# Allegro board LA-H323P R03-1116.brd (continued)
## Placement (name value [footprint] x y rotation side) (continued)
RC460  15_0402_5%  [R_0402]  96.63 36.27 90 bottom
RC462  0_0402_5%  [R_0402]  89.9 34.55 90 bottom
RC467  1K_0201_5%  [R_0201]  117.2 39.85 180 top
RC468  1K_0201_5%  [R_0201]  116.31 41.78 270 top
RC469  1K_0201_5%  [R_0201]  83.68 25.25 90 top
RC470  1K_0201_5%  [R_0201]  85.38 25.25 90 top
RC471  BLM15PX221SN1D 0402  [MURAT_BLM15EG221SN1D_2P]  127.87 54.29 180 top
RC472  4.7K_0201_5%  [R_0201]  113.52 35.3 270 bottom
RC473  20K_0201_5%  [R_0201]  114.24 35.26 0 bottom
RC474  4.7K_0201_5%  [R_0201]  101.62 42.02 0 top
RC475  10K_0201_5%  [R_0201]  102.85 43.24 270 top
RC477  0_0402_5%  [R_0402]  128.2 39.33 180 top
RC480  1K_0402_1%  [R_0402]  131.89 81.82 90 bottom
RC481  1K_0402_1%  [R_0402]  126.45 87.09 90 top
RC482  1K_0402_1%  [R_0402]  131.71 83.6 90 bottom
RC483  100K_0201_5%  [R_0201]  101.22 48.49 180 bottom
RC484  49.9_0402_1%  [R_0402]  123.15 87.09 90 top
RC485  49.9_0402_1%  [R_0402]  123.97 87.09 90 top
RC486  1K_0402_1%  [R_0402]  132.67 82.73 270 bottom
RC487  1K_0402_1%  [R_0402]  130.73 82.73 270 bottom
RC488  1K_0402_1%  [R_0402]  130.17 85.72 270 bottom
RC489  1K_0402_1%  [R_0402]  129.96 82.73 270 bottom
RC491  4.7K_0201_5%  [R_0201]  112.76 35.3 270 bottom
RC492  0_0201_5%  [R_0201]  92.53 43.77 0 top
RC900  10K_0402_5%  [R_0402]  101.71 37.03 90 bottom
RC901  10K_0402_5%  [R_0402]  101.71 35.25 90 bottom
RC916  10K_0201_5%  [R_0201]  100.19 36.94 90 bottom
RC926  10K_0201_5%  [R_0201]  100.95 42.65 90 top
RC934  0_0402_5%  [R_0402]  162.03 21.31 270 top
RC935  49.9_0201_1%  [R_0201]  129.96 76.89 0 bottom
RC936  10K_0201_5%  [R_0201]  114.32 42.44 180 top
RC937  100_0402_5%  [R_0402]  131.52 87.09 90 top
RC938  0_0402_5%  [R_0402]  85.38 38.5 0 top
RC940  10K_0201_5%  [R_0201]  100.19 35.67 90 bottom
RC941  100K_0201_5%  [R_0201]  97.14 40.67 270 bottom
RC942  49.9_0402_1%  [R_0402]  121.57 34.63 0 bottom
RC943  49.9_0402_1%  [R_0402]  122.21 31.52 0 bottom
RC944  49.9_0402_1%  [R_0402]  128.56 34.18 0 bottom
RC945  49.9_0402_1%  [R_0402]  127.82 35.96 180 bottom
RC946  49.9_0402_1%  [R_0402]  127.76 34.18 180 bottom
RC947  49.9_0402_1%  [R_0402]  123.12 30.63 180 bottom
RC948  49.9_0402_1%  [R_0402]  125.9 35.66 270 bottom
RC949  33_0402_5%  [R_0402]  100.28 55.64 0 bottom
RC950  33_0402_5%  [R_0402]  100.08 56.41 0 bottom
RC951  33_0402_5%  [R_0402]  100.28 53.97 0 bottom
RC952  10K_0201_5%  [R_0201]  105.27 42.4 90 top
RC953  10K_0201_5%  [R_0201]  106.54 42.4 90 top
RC954  10K_0201_5%  [R_0201]  105.27 41.13 90 top
RC955  10K_0201_5%  [R_0201]  107.17 42.4 90 top
RC956  10K_0201_5%  [R_0201]  98.83 50.88 180 bottom
RC957  10K_0201_5%  [R_0201]  129.69 40.66 180 bottom
RC958  10K_0201_5%  [R_0201]  100.24 52.39 0 bottom
RC959  10K_0201_5%  [R_0201]  123.43 36.94 90 top
RC961  10K_0201_5%  [R_0201]  123.3 39.56 270 top
RC962  10K_0201_5%  [R_0201]  124.48 38.37 180 bottom
RC963  10K_0201_5%  [R_0201]  123.93 42.98 270 top
RC964  10K_0201_5%  [R_0201]  121.52 42.98 270 top
RC965  10K_0201_5%  [R_0201]  123.17 42.98 270 top
RC966  10K_0201_5%  [R_0201]  122.28 42.98 270 top
RC967  0_0402_5%  [R_0402]  87.92 34.75 0 top
RC977  0_0402_5%  [R_0402]  114.6 36.58 90 bottom
RC978  10K_0201_5%  [R_0201]  121.99 38.37 0 bottom
RC979  100K_0201_5%  [R_0201]  98.83 50.12 180 bottom
RC980  10K_0402_5%  [R_0402]  101.19 55.56 180 top
RC983  100K_0201_5%  [R_0201]  99.04 43.24 270 top
RC984  100K_0201_5%  [R_0201]  99.54 43.73 180 bottom
RC985  20K_0201_5%  [R_0201]  108.82 42.4 90 top
RC986  100K_0201_5%  [R_0201]  99.55 36.25 270 bottom
RC987  100K_0201_5%  [R_0201]  96.67 53.93 180 bottom
RC1154  71.5K_0402_1%  [R_0402]  113.62 35.2 180 top
RC1155  20K_0201_5%  [R_0201]  117.94 38.06 180 bottom
RC1156  499_0402_1%  [R_0402]  99.11 54.54 180 bottom
RC1157  100K_0402_5%  [R_0402]  132.23 86.23 180 bottom
RC1158  1K_0201_5%  [R_0201]  86.01 25.25 90 top
RC1159  1K_0201_5%  [R_0201]  84.31 25.25 90 top
RC1160  49.9_0402_1%  [R_0402]  120.47 33.57 180 bottom
RD1  0_0402_5%  [R_0402]  51.94 26.13 270 top
RD2  0_0402_5%  [R_0402]  52.05 48.2 90 top
RD3  0_0402_5%  [R0402_0OHM]  52.85 25.22 90 top
RD4  0_0402_5%  [R_0402]  54.66 26.13 270 top
RD5  0_0402_5%  [R0402_0OHM]  53.75 25.22 90 top
RD6  0_0402_5%  [R0402_0OHM]  51.16 49.12 270 top
RD7  240_0402_1%  [R_0402]  53.75 60.47 0 top
RD8  1K_0402_1%  [R_0402]  55.08 50.75 180 top
RD9  2_0402_1%  [R_0402]  55.08 51.67 180 top
RD10  1K_0402_1%  [R_0402]  55.08 49.84 180 top
RD11  24.9_0402_1%  [R_0402]  56.75 52.68 180 top
RD19  0_0402_5%  [R_0402]  38.71 22.91 90 top
RD20  0_0402_5%  [R0402_0OHM]  39.6 22.91 90 top
RD21  0_0402_5%  [R_0402]  41.55 45.98 90 top
RD22  0_0402_5%  [R0402_0OHM]  39.54 24.76 180 top
RD23  0_0402_5%  [R_0402]  40.41 24.77 0 top
RD24  0_0402_5%  [R0402_0OHM]  40.65 46.89 270 top
RD25  240_0402_1%  [R_0402]  40.42 59.71 0 top
RD26  1K_0402_1%  [R_0402]  41.51 52.14 90 top
RD27  2_0402_1%  [R_0402]  40.62 52.14 90 top
RD28  1K_0402_1%  [R_0402]  41.58 50.64 180 top
RD29  24.9_0402_1%  [R_0402]  38.69 52.59 90 top
RD32  0_0402_5%  [R0402_0OHM]  65.69 28.42 270 top
RD33  0_0402_5%  [R0402_0OHM]  48.88 28.93 270 top
RE50  10K_0402_5%  [R_0402]  241.54 19.88 90 bottom
RE51  10K_0402_5%  [R_0402]  239.81 21.61 0 bottom
RF1  0_0402_5%  [R0402_0OHM]  253.77 30.3 270 bottom
RG10  15 +-1% 0402  [R_0402]  18.75 115.92 180 bottom
RG12  15 +-1% 0402  [R_0402]  18.75 121.23 180 bottom
RG13  15 +-1% 0402  [R_0402]  18.75 122.02 180 bottom
RG47  1M_0402_5%  [R_0402]  20.13 125.88 180 top
RG56  20K_0402_5%  [R_0402]  19.34 129.94 0 top
RG59  15 +-1% 0402  [R_0402]  18.75 118.18 180 bottom
RG60  15 +-1% 0402  [R_0402]  18.75 118.97 180 bottom
RG61  15 +-1% 0402  [R_0402]  18.75 112.08 180 bottom
RG63  15 +-1% 0402  [R_0402]  18.75 112.87 180 bottom
RG65  15 +-1% 0402  [R_0402]  18.75 115.13 180 bottom
RG67  10K_0402_5%  [R_0402]  175.95 123.59 180 top
RG105  2.2K_0402_5%  [R_0402]  13.5 129.43 0 top
RG108  10K_0402_5%  [R_0402]  18.14 128.75 270 top
RG109  2.2K_0402_5%  [R_0402]  13.5 130.2 0 top
RG110  2.2K_0402_5%  [R_0402]  15.98 131.53 0 top
RG111  2.2K_0402_5%  [R_0402]  16.32 127.85 180 top
RG112  470_0201_5%  [R_0201]  20.21 111.27 180 bottom
RG113  470_0201_5%  [R_0201]  20.21 113.69 180 bottom
RG114  470_0201_5%  [R_0201]  20.21 114.32 180 bottom
RG115  470_0201_5%  [R_0201]  20.21 116.73 180 bottom
RG116  470_0201_5%  [R_0201]  20.21 117.37 180 bottom
RG117  470_0201_5%  [R_0201]  20.21 119.78 180 bottom
RG118  470_0201_5%  [R_0201]  20.21 120.42 180 bottom
RG119  470_0201_5%  [R_0201]  20.21 122.83 180 bottom
RK1  0_0603_5%  [R0603_0OHM]  149.87 48.93 180 bottom
RK2  100K_0402_1%  [R_0402]  168.13 28.16 270 bottom
RK3  0_0402_5%  [R0402_0OHM]  150.3 45.08 180 bottom
RK4  33K_0402_1%  [R_0402]  169.02 27.25 90 bottom
RK6  0_0402_5%  [R_0402]  172.47 42.69 180 bottom
RK7  330K_0402_5%  [R_0402]  171.56 44.47 0 bottom
RK8  0_0201_5%  [R0201_0OHM]  148.27 36.6 180 bottom
RK9  0_0201_5%  [R0201_0OHM]  148.27 35.71 180 bottom
RK10  0_0402_5%  [R_0402]  172.47 41.88 180 bottom
RK12  4.7K_0402_5%  [R_0402]  158.52 30.35 0 top
RK13  4.7K_0402_5%  [R_0402]  158.52 31.11 0 top
RK14  10K_0402_5%  [R_0402]  161.98 50.34 270 bottom
RK17  43_0402_1%  [R_0402]  150.3 41.87 180 bottom
RK21  10K_0402_5%  [R_0402]  167.24 27.25 90 bottom
RK26  100K_0402_5%  [R_0402]  165.58 49.98 180 bottom
RK27  100K_0402_5%  [R_0402]  150.3 40.85 180 bottom
RK28  100K_0402_5%  [R_0402]  171.56 45.36 0 bottom
RK108  10K_0402_5%  [R_0402]  163.67 50.85 270 bottom
RK109  22_0402_5%  [R_0402]  158.59 50.36 270 bottom
RK110  2.2K_0402_5%  [R_0402]  162.92 30.96 270 top
RK111  2.2K_0402_5%  [R_0402]  162.03 30.96 270 top
RK112  2.2K_0402_5%  [R_0402]  161.78 34.77 270 top
RK113  2.2K_0402_5%  [R_0402]  160.89 34.77 270 top
RK115  10K_0402_5%  [R_0402]  160.5 50.36 270 bottom
RK116  100K_0402_5%  [R_0402]  149.36 39 0 bottom
RK117  100K_0402_5%  [R_0402]  145.75 36.08 270 bottom
RL7  1M_0402_5%  [R_0402]  33.43 102.76 0 bottom
RL11  2.49K_0402_1%  [R_0402]  30.63 103 90 bottom
RL15  10K_0402_5%  [R_0402]  41.57 106.7 180 bottom
RL30  374 +-5% 0402  [R_0402]  37.79 100.65 90 bottom
RL31  510_0402_5%  [R_0402]  36.01 100.65 90 bottom
RL55  0_0805_5%  [R0805_0OHM]  30.63 132.48 0 top
RL56  4.7K_0402_5%  [R_0402]  36.9 101.56 270 bottom
RL57  75_0402_1%  [R_0402]  26.14 127.1 270 top
RL58  75_0402_1%  [R_0402]  25.26 127.1 270 top
RL59  75_0402_1%  [R_0402]  25.26 124.53 90 top
RL60  75_0402_1%  [R_0402]  26.14 124.53 90 top
RLED1  680_0402_1%  [R_0402]  5.57 84.32 270 top
RLED2  220_0402_5%  [R_0402]  6.45 93.39 0 bottom
RLED3  0_0402_5%  [R0402_0OHM]  5.82 93.57 270 top
RM6  1K_0402_5%  [R_0402]  41.57 108.22 180 bottom
RM11  15K_0402_5%  [R_0402]  38.67 109.18 270 top
RN3  10K_0402_5%  [R_0402]  225.8 5.18 180 top
RN7  4.7K_0402_5%  [R_0402]  226.28 21.36 0 top
RN15  10K_0402_5%  [R_0402]  230.95 7.76 180 bottom
RS21  100K_0402_5%  [R_0402]  179.22 43.84 90 bottom
RS22  10K_0402_5%  [R_0402]  180.16 44.75 270 bottom
RS46  10K_0402_5%  [R_0402]  190.53 41.5 180 top
RS47  0_0201_5%  [R_0201]  219.43 36.94 90 top
RS48  0_0201_5%  [R_0201]  220.06 36.94 90 top
RS49  0_0201_5%  [R_0201]  217.6 36.94 90 top
RS50  0_0201_5%  [R_0201]  218.23 36.94 90 top
RS53  0_0201_5%  [R_0201]  255.76 20.07 0 bottom
RS54  0_0201_5%  [R_0201]  255.76 19.44 0 bottom
RT3  0_0201_5%  [R0201_0OHM]  203.18 39.56 270 top
RT6  33_0402_5%  [R_0402]  121.57 35.71 0 bottom
RT7  33_0402_5%  [R_0402]  150.91 24.12 0 top
RT8  33_0402_5%  [R_0402]  122.21 32.41 0 bottom
RT9  33_0402_5%  [R_0402]  128.56 35.07 0 bottom
RT10  4.7K_0402_5%  [R_0402]  162.03 22.68 90 top
RT11  100K_0402_5%  [R_0402]  65.53 102.72 90 top
RT12  4.7K_0402_5%  [R_0402]  160.18 24.53 0 top
RT34  0_0201_5%  [R0201_0OHM]  66.25 102.72 270 top
RT35  4.7K_0402_5%  [R_0402]  161.1 23.64 180 top
RU1  100K_0402_1%  [R_0402]  6.97 85.29 90 bottom
RU2  100K_0402_5%  [R_0402]  6.02 82.25 90 bottom
RU3  47K_0402_5%  [R_0402]  6.84 83.21 270 bottom
RV4  200_0402_1%  [R_0402]  137.02 110.1 180 top
RV15  10K_0402_5%  [R_0402]  162.92 90.06 180 bottom
RV16  0_0402_5%  [R_0402]  181.59 128.29 180 top
RV17  10K_0402_5%  [R_0402]  181.59 129.18 180 top
RV20  10K_0402_1%  [R_0402]  159.17 99.18 0 bottom
RV21  10K_0402_1%  [R_0402]  159.17 99.95 0 bottom
RV23  10K_0402_1%  [R_0402]  159.17 98.42 0 bottom
RV26  10K_0402_5%  [R_0402]  160.97 88.39 180 bottom
RV30  10K_0402_5%  [R_0402]  171.89 92.22 180 top
RV31  0_0402_5%  [R0402_0OHM]  170.22 91.13 0 bottom
RV41  40.2_0402_1%  [R_0402]  163.23 115.72 0 top
RV42  40.2_0402_1%  [R_0402]  164.14 116.61 180 top
RV43  60.4_0402_1%  [R_0402]  164.14 117.5 180 top
RV51  4.99K_0402_1%  [R_0402]  153.05 88.44 90 bottom
RV61  10K_0402_1%  [R_0402]  154.72 88.44 90 bottom
RV64  4.99K_0402_1%  [R_0402]  171.92 96.02 180 top
RV65  4.99K_0402_1%  [R_0402]  169.82 95.31 0 bottom
RV67  10K_0402_5%  [R_0402]  172.84 93.15 0 top
RV68  10K_0402_5%  [R_0402]  179.81 127.53 180 top
RV69  100K_0402_5%  [R_0402]  180.58 125.81 90 top
RV70  10K_0402_5%  [R_0402]  157.64 88.67 0 bottom
RV71  10K_0402_5%  [R_0402]  136.13 99.77 0 top
RV72  10K_0402_5%  [R_0402]  156.45 89.35 270 bottom
RV80  4.99K_0402_1%  [R_0402]  173.75 94.04 180 top
RV81  4.99K_0402_1%  [R_0402]  173.75 96.02 180 top
RV82  60.4_0402_1%  [R_0402]  151.36 111.11 270 top
RV83  60.4_0402_1%  [R_0402]  148.26 111.44 270 top
RV84  14.7K_0402_1%  [R_0402]  169.65 99.03 270 bottom
RV85  1K_0402_5%  [R_0402]  132.16 122.45 0 bottom
RV88  10K_0402_5%  [R_0402]  170.7 93.15 0 bottom
RV102  100K_0402_5%  [R_0402]  153.67 96.16 180 top
RV116  1K_0402_1%  [R_0402]  156.83 131.55 90 top
RV117  1K_0402_1%  [R_0402]  146.04 132.67 90 top
RV118  1K_0402_1%  [R_0402]  164.33 132.18 90 top
RV119  1K_0402_1%  [R_0402]  132.68 132.59 270 top
RV120  121_0402_1%  [R_0402]  171.74 132.4 180 bottom
RV121  121_0402_1%  [R_0402]  131.92 132.08 270 bottom
RV123  80.6_0402_1%  [R_0402]  167.37 131.95 270 top
RV125  549_0402_1%  [R_0402]  172.63 126.16 0 bottom
RV126  0_0402_5%  [R_0402]  162.92 89.17 180 bottom
RV127  1.33K_0402_1%  [R_0402]  173.55 127.05 180 bottom
RV175  80.6_0402_1%  [R_0402]  136.46 133.77 180 top
RV200  931_0402_1%  [R_0402]  172.63 125.27 0 bottom
RV201  0_0402_5%  [R_0402]  170.07 96.95 0 bottom
RV202  0_0402_5%  [R0402_0OHM]  170.21 91.98 0 bottom
RV203  2.2K_0402_5%  [R_0402]  165.59 92.79 270 bottom
RV204  2.2K_0402_5%  [R_0402]  161.1 91.06 180 bottom
RV205  2.2K_0402_5%  [R_0402]  159.17 97.66 0 bottom
RV206  2.2K_0402_5%  [R_0402]  159.17 96.9 0 bottom
RV217  100_0402_1%  [R_0402]  115.73 136.34 0 top
RV218  100_0402_1%  [R_0402]  117.38 140.61 0 top
RV375  0_0402_5%  [R_0402]  177.4 127.53 180 top
RV376  2.49K_0402_1%  [R_0402]  132.19 112.6 270 bottom
RV377  0_0402_5%  [R0402_0OHM]  136.65 104.36 90 top
RV378  10K_0402_5%  [R_0402]  181.49 123.51 90 top
RV379  0_0402_5%  [R_0402]  180.58 124.43 270 top
RV380  40.2K_0402_1%  [R_0402]  152.9 101.09 90 top
RV381  4.99K_0402_1%  [R_0402]  171.92 94.05 180 top
RV382  4.99K_0402_1%  [R_0402]  155.64 88.44 90 bottom
RV383  4.99K_0402_1%  [R_0402]  153.81 90.17 90 bottom
RV384  49.9K_0402_1%  [R_0402]  153.81 88.44 90 bottom
RV385  45.3K_0402_1%  [R_0402]  154.72 90.17 90 bottom
RV387  4.99K_0402_1%  [R_0402]  152.13 90.17 90 bottom
RV388  4.99K_0402_1%  [R_0402]  155.64 90.17 90 bottom
RV389  45.3K_0402_1%  [R_0402]  152.13 88.44 90 bottom
RV390  4.99K_0402_1%  [R_0402]  153.05 90.17 90 bottom
RV579  4.7K_0402_5%  [R_0402]  160.97 89.28 180 bottom
RV2437  10K_0402_5%  [R_0402]  147.03 131.29 90 bottom
RV2438  10K_0402_5%  [R_0402]  155.79 130.16 90 bottom
RV2439  10K_0402_5%  [R_0402]  155.56 132.06 180 bottom
RV2440  10K_0402_5%  [R_0402]  147.92 132.97 270 bottom
RV2739  47K_0402_5%  [R_0402]  196.07 126.97 270 top
RV2741  10K_0402_5%  [R_0402]  194.24 127.78 180 top
RV2745  47K_0402_5%  [R_0402]  196.07 124.4 90 top
RV2746  10K_0402_5%  [R_0402]  188.55 127.53 0 top
RV2747  0_0402_5%  [R_0402]  193.33 128.67 0 top
RV2748  0_0402_5%  [R_0402]  195.89 123.59 180 top
RV2751  0_0402_5%  [R_0402]  152.13 102 270 top
RV2752  47K_0402_5%  [R_0402]  132.16 123.34 0 bottom
RV2753  10K_0402_5%  [R_0402]  181.49 125.81 90 top
RV2758  2.2K_0402_5%  [R_0402]  156.9 91.08 270 bottom
RV2759  2.2K_0402_5%  [R_0402]  157.72 91.08 270 bottom
RV2760  2.2K_0402_5%  [R_0402]  158.55 91.08 270 bottom
RV2761  2.2K_0402_5%  [R_0402]  159.37 91.08 270 bottom
RV2762  10K_0402_5%  [R_0402]  153.23 97.22 180 top
RV2763  10K_0402_5%  [R_0402]  153.23 98.05 180 top
RV2764  10K_0402_5%  [R_0402]  153.23 98.88 180 top
RV2765  10K_0402_5%  [R_0402]  163.94 91.54 180 top
RV2766  10K_0402_5%  [R_0402]  149.09 92.03 270 bottom
RV2767  10K_0402_5%  [R_0402]  131.05 94.3 90 bottom
RV2768  10K_0402_5%  [R_0402]  149.91 92.03 270 bottom
RW3  0_0402_5%  [R_0402]  230.03 19.42 0 bottom
RW4  0_0402_5%  [R_0402]  230.03 18.48 0 bottom
RW5  22_0402_5%  [R_0402]  230.03 15.76 0 bottom
RW6  75_0402_5%  [R_0402]  118.09 35.76 90 bottom
RW7  22_0402_5%  [R_0402]  230.03 10.45 0 bottom
RW8  75_0402_5%  [R_0402]  118.91 35.76 90 bottom
RW11  0_0402_5%  [R_0402]  230.03 17.59 0 bottom
RW12  0_0402_5%  [R_0402]  230.03 12.2 0 bottom
RWL1  200K_0402_5%  [R_0402]  248.01 20.52 90 bottom
RWL2  1K_0402_5%  [R_0402]  231 22.23 90 top
SW1  SW TJG-533KQRH SPST DIP H1.55 6P  [SW_TJG-533-V-T-R_6P]  19.8 110.75 180 top
T62  PAD~D  [TPC12]  98.32 46.06 180 bottom
T63  PAD~D  [TPC12]  98.31 47.34 180 bottom
T78  PAD~D  [TPC12]  129.4 78.63 180 bottom
T79  PAD~D  [TPC12]  122.64 76.75 0 top
T81  PAD~D  [TPC12]  99.53 46.46 180 bottom
T90  PAD~D  [TPC12]  97.65 41.3 0 top
T96  PAD~D  [TPC12]  127.63 77.32 180 bottom
T103  PAD~D  [TPC12]  128.98 77.43 180 bottom
T140  PAD~D  [TPC12]  129.05 67.81 180 bottom
T178  PAD~D  [TPC12]  127.66 76.04 90 bottom
T231  PAD  [TPC12]  134.63 97.98 0 top
T232  PAD  [TPC12]  136.18 96.71 0 top
T242  PAD  [TPC12]  135.94 98.56 0 top
T243  PAD  [TPC12]  128.86 95.79 0 top
T254  PAD~D  [TPC12]  95.5 43.71 0 top
T257  PAD~D  [TPC12]  108.2 53.23 0 top
T258  PAD~D  [TPC12]  102.8 52.6 0 top
T276  PAD~D  [TPC12]  121.42 68.31 0 top
T305  PAD~D  [TPC12]  114.66 43.35 0 top
T306  PAD~D  [TPC12]  128.04 64.81 180 bottom
T307  PAD~D  [TPC12]  129.32 64.81 180 bottom
T323  PAD~D  [TPC12]  128.96 81.26 180 bottom
T324  PAD~D  [TPC12]  128.99 82.54 180 bottom
T325  PAD~D  [TPC12]  130.32 80.74 180 bottom
T326  PAD~D  [TPC12]  124.04 80.05 0 top
T327  PAD~D  [TPC12]  120.37 43.52 0 top
T328  PAD~D  [TPC12]  120.14 39.77 0 top
T329  PAD~D  [TPC12]  120.21 41.08 0 top
T354  PAD~D  [TPC12]  100.64 47.62 180 bottom
T365  PAD~D  [TPC12]  128.05 78.53 180 bottom
T366  PAD~D  [TPC12]  127.96 79.83 180 bottom
T367  PAD~D  [TPC12]  131.99 80.87 180 bottom
T368  PAD~D  [TPC12]  129.23 79.99 180 bottom
T369  PAD~D  [TPC12]  129.12 83.85 180 bottom
T370  PAD~D  [TPC12]  127.73 82.35 180 bottom
T371  PAD~D  [TPC12]  130.45 83.86 180 bottom
T372  PAD~D  [TPC12]  127.68 81.07 180 bottom
T377  PAD~D  [TPC12]  102.48 32.89 180 bottom
T402  PAD~D  [TPC12]  15.24 82.95 180 bottom
T403  PAD~D  [TPC12]  13.86 83.66 180 bottom
T404  PAD~D  [TPC12]  13.79 87.41 180 bottom
T405  PAD~D  [TPC12]  14.46 86.25 180 bottom
T406  PAD~D  [TPC12]  13.83 85.08 180 bottom
T408  PAD~D  [TPC12]  121.98 41.55 0 top
T2401  PAD  [TPC12]  154.29 112.52 0 top
T2404  PAD~D  [TPC12]  122.49 39.36 180 bottom
T2405  PAD~D  [TPC12]  121.13 39.57 180 bottom
T2406  PAD~D  [TPC12]  103.49 33.76 180 bottom
TS123  PAD  [TPC12]  188.91 39.78 0 top
TSL1  LAN-8100G 1G  [TAI-T_LAN-8700GS_25P]  31.95 130.08 270 bottom
U4018  APX8131AI-TRG SOT-23  [YB8251ST23_TSOT-23-3]  16.85 138.4 0 top
UA1  -  [ALC3247-CG_MQFN40_5X5]  21.81 40.24 270 top
UC1  WHL-U42_BGA1528  [WHL-U42_BGA_1528P-T]  125.94 86.13 180 bottom
UC2  W25Q128JVSIQ SOP 8P  [ACES_91960-0084L_8P-T]  126.09 32.02 180 bottom
UC3  74AUP1G07DCKR SC70  [74AUP1G07GW_TSSOP5]  112.88 94.37 90 bottom
UC4  TC7SH08FU_SSOP5  [SN74AHC1G08DCKR_SC70-5]  94.09 30.45 270 bottom
UC6  EM5209VF_DFN14_2X3  [TPS22966DPUR_SON14_2X3]  144.83 40.91 0 top
UC7  AOZ1334DI-01 DFN 8P  [TPS22961DNYR_WSON8]  116.02 99.67 180 top
UC11  -  [G753T11U_SOT23-5]  172.61 110.37 180 bottom
UG1  -  [G2895TP1U_TSOT23-6]  63.76 111.59 270 top
UK1  KB9022QD_LQFP128_14X14  [KB9022QC_LQFP128_14X14]  154.57 47.6 270 bottom
UL1  RTL8111HSH-CG  [RTL8166EH-CG_QFN32_4X4]  31.33 106.06 90 bottom
UL2  -  [G524B1T11U_SOT23-5]  43.31 106.29 0 bottom
UT1  SLB9670VQ1.2 FW6.40_VQFN32_5X5  [SLB9670VQ1P2-FW4P4X_VQFN32_5X5]  158.74 21.89 180 top
UU1  -  [TPS25810RVCR_QFN20_4X3]  11.53 83.41 180 bottom
UU2  G518A1TO1U_SOT23-5  [G524B2T11U_SOT23-5]  11.35 91.56 0 bottom
UV1  N16S-GT-S-A2_BGA595  [N16S-GT-S-A2_BGA_595P]  155.9 94.3 90 bottom
UV6  MT51J256M32HF-60:A  [H5GQ1H24AFR-T2L_BGA_170P]  158.13 125.11 0 bottom
UV7  MT51J256M32HF-60:A  [H5GQ1H24AFR-T2L_BGA_170P]  144.68 138.91 180 bottom
UV12  TC7SH08FU_SSOP5  [TC7SH08FUF_SSOP5]  182.7 127.8 270 top
UV15  TC7SH08FU_SSOP5  [TC7SH08FUF_SSOP5]  182.7 125.13 270 top
UV23  MC74VHC1G32DFT2G SC70-5  [NC7ST32P5X_SC70-5]  173.09 94.03 180 bottom
YC1  32.768KHZ_9PF  [Y_1TJF125BJ1A000A_2P]  106.63 35.75 180 bottom
YC2  24MHZ 18PF XRCGB24M000F2P51R0  [Y_XRCGB24M000F2P51R0_4P]  131.79 42.33 90 bottom
YL1  25MHZ 10PF XRCGB25M000F2P34R0  [Y_XRCGB25M000F2P34R0_4P]  34.44 99.87 180 bottom
YV1  27MHZ_10PF_XRCGB27M000F2P18R0  [Y_XRCGB27M000F2P18R0_4P]  162.03 102.78 270 bottom

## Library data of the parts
C11-C14 C19 C117 C118 C140 C153-C156 C193 C554 C557 C570 C575 C593 C594 C4801 C5181-C5186 C5214 C5221 C5222 C5228 C5230-C5233 CA5-CA13 CA19-CA23 CA27-CA30 CA32-CA34 CA36 CA37 CA39 CA41-CA47 CC12 CC13 CC15 CC16 CC27 CC28 CC37-CC42 CC57-CC60 CC88 CC94 CC95 CC122 CC123 CC144 CC154 CC159 CC163 CC256 CC276-CC283 CC292 CC293 CC295 CC297-CC303 CC312 CC314 CC315 CC320 CC325 CC346-CC350 CC354-CC359 CD3 CD4 CD7 CD8 CD10 CD15-CD23 CD62 CD63 CD66 CD67 CD73-CD80 CD82 CD92 CD93 CD95 CE24 CG2 CG8-CG15 CG46 CG47 CK4 CK5 CK8-CK10 CL1 CL3-CL5 CL8-CL14 CL16 CL19 CL20 CL23-CL26 CL28 CL29 CLED1 CLED2 CM17 CM26 CM27 CN3-CN5 CR11 CR13 CS31-CS34 CSS7 CT1 CT3 CT4 CT97 CT98 CT100-CT103 CTS1 CTS3 CTS6 CTS7 CU6-CU11 CV2-CV6 CV8 CV11-CV18 CV20 CV22 CV30 CV38 CV44-CV46 CV51 CV158-CV160 CV165-CV168 CV173-CV175 CV190 CV198 CV199 CV203 CV204 CV209 CV210 CV213 CV216 CV217 CV312 CV315 CV319 CV373-CV388 CV393-CV396 CWL1 CWL2 PC1-PC6 PC8-PC11 PC302-PC304 PC310-PC313 PC316-PC318 PC324-PC327 PC331 PC1003-PC1005 PC1007-PC1010 PC1802 PC1805 PC1806 PC2502-PC2504 PC2507 PCA1-PCA3 PCA6-PCA8 PCB1 PCB4 PCB5 PCB8-PCB14 PCB17-PCB25 PCG1 PCG2 PCG4 PCG8 PCG9 PCG12 PCM1 PCM4-PCM6 PCM14 PCM15 PCM17 PCM18 PCV1 PCV9-PCV14 PCV18-PCV22 PCV24-PCV26 PCV37-PCV51 PCV56 PCV57 PCW2 PCW3 PCW6 PCW7 PCW9 PCW10 PCZ3-PCZ7 PCZ9 PCZ11-PCZ13 PCZ15 PCZ16 PCZ18-PCZ21 PCZ23 PCZ28-PCZ30 PCZ33 PCZ35 PCZ36 PCZ40-PCZ45 PCZ227 PCZ228 PCZ230-PCZ232 R5179 R5180 = C_0402
C18 CA15 CA16 CA31 CA48 CC7-CC11 CC14 CC19 CC20 CC29-CC36 CC43-CC46 CC48-CC51 CC55 CC61-CC63 CC67 CC68 CC71-CC74 CC76 CC80 CC86 CC87 CC89-CC91 CC96-CC98 CC102 CC103 CC117 CC127 CC141 CC142 CC184-CC187 CC261 CC269 CC270 CC274 CC275 CC288-CC291 CC296 CC316 CC319 CC321 CC323 CC324 CC326-CC328 CC331-CC339 CC341-CC343 CC351-CC353 CC360-CC366 CD1 CD2 CD5 CD6 CD9 CD11-CD14 CD24-CD31 CD60 CD61 CD64 CD65 CD68-CD72 CD81 CD83-CD90 CD94 CD96-CD100 CG1 CG3 CG4 CG75-CG78 CK1-CK3 CK11 CL15 CL27 CS1 CS2 CS8-CS10 CS23 CS24 CSS5 CSS6 CT2 CT5 CU4 CU12 CV31 CV34 CV52 CV53 CV55 CV60 CV121 CV133 CV161-CV164 CV169-CV172 CV200-CV202 CV205-CV208 CV211 CV212 CV214 CV215 CV218-CV223 CV311 CV313 CV314 CV316-CV318 CV320 CV321 CV389-CV392 PC1006 PC1016 PCM3 PCM7 PCM16 PCM19-PCM21 PCV28-PCV32 PCW1 PCW4 PCW8 PCW16 PCZ140-PCZ146 PCZ167-PCZ214 = C_0201
C174 = C_MP2VLPS330MC4R2
CA24-CA26 CC82 CC111 CC112 CC115 CC116 CC134 CC140 CC317 CC318 CC329 CS27 CU3 CV7 CV10 CV35 CV61 PC301 PC305-PC309 PC314 PC315 PC319 PC322 PC323 PC328-PC330 PC1001 PC1011-PC1014 PC1801 PC1803 PC1804 PC2501 PC2505 PC2506 PCA4 PCA5 PCG5 PCG10 PCM2 PCM8-PCM13 PCV52 PCV58-PCV61 PCV66-PCV76 PCW5 PCW11-PCW14 PCW17-PCW19 PCZ1 PCZ31 PCZ32 PCZ34 PCZ37 PCZ47 PCZ70-PCZ82 PCZ85-PCZ91 PCZ93-PCZ104 PCZ109-PCZ117 PCZ119 PCZ127 PCZ131 PCZ132 PCZ134-PCZ137 PCZ150 PCZ154 PCZ155 PCZ157-PCZ166 PCZ233-PCZ240 PCZ243-PCZ247 = C_0603
CC81 CC170 CC171 CU13 PCV53 = C_0805
CG71-CG74 PH1 PHA1 PHG1 PHZ1-PHZ3 PR1-PR6 PR9 PR10 PR13-PR17 PR20 PR21 PR301 PR304 PR305 PR307 PR309 PR310 PR312 PR313 PR1002 PR1004 PR1005 PR1008-PR1010 PR1801 PR1803 PR1805 PR1806 PR2502-PR2507 PRA1 PRA7 PRA8 PRB2 PRB3 PRB15-PRB17 PRB20 PRB21 PRG1 PRG7 PRG8 PRM2 PRM6 PRM7 PRM9-PRM11 PRV3 PRV5 PRV6 PRV8-PRV11 PRV13-PRV15 PRV18 PRV22 PRV24 PRV26-PRV33 PRW1-PRW5 PRW8-PRW10 PRZ1-PRZ6 PRZ8 PRZ10 PRZ11 PRZ13 PRZ14 PRZ17-PRZ24 PRZ26 PRZ28-PRZ31 PRZ33 PRZ35 PRZ36 PRZ38 PRZ39 PRZ41 PRZ43 PRZ45 PRZ48 PRZ49 PRZ51 PRZ52 PRZ54 PRZ56 PRZ59 PRZ63-PRZ75 PRZ80 PRZ81 PRZ88 PRZ90 PRZ98-PRZ100 PRZ104-PRZ109 R23 R28 R126 R166 R203 R207 R215 R295 R1088 R1089 R5092 R5093 R5176 R5187 R5201 R5202 R5273 RA1 RA2 RA4-RA10 RA13-RA17 RA23 RA24 RA26 RA37-RA42 RA53 RC1-RC3 RC5 RC6 RC14 RC32 RC38-RC40 RC72 RC76 RC81 RC82 RC92 RC96 RC98 RC102 RC113 RC116 RC119 RC120 RC142 RC150 RC154 RC173 RC179-RC181 RC185 RC188 RC193 RC215 RC216 RC369 RC388-RC391 RC393 RC398 RC399 RC402 RC421 RC429 RC447 RC448 RC456 RC457 RC460 RC462 RC477 RC480-RC482 RC484-RC489 RC900 RC901 RC934 RC937 RC938 RC942-RC951 RC967 RC977 RC980 RC1154 RC1156 RC1157 RC1160 RD1 RD2 RD4 RD7-RD11 RD19 RD21 RD23 RD25-RD29 RE50 RE51 RG10 RG12 RG13 RG47 RG56 RG59-RG61 RG63 RG65 RG67 RG105 RG108-RG111 RK2 RK4 RK6 RK7 RK10 RK12-RK14 RK17 RK21 RK26-RK28 RK108-RK113 RK115-RK117 RL7 RL11 RL15 RL30 RL31 RL56-RL60 RLED1 RLED2 RM6 RM11 RN3 RN7 RN15 RS21 RS22 RS46 RT6-RT12 RT35 RU1-RU3 RV4 RV15-RV17 RV20 RV21 RV23 RV26 RV30 RV41-RV43 RV51 RV61 RV64 RV65 RV67-RV72 RV80-RV85 RV88 RV102 RV116-RV121 RV123 RV125-RV127 RV175 RV200 RV201 RV203-RV206 RV217 RV218 RV375 RV376 RV378-RV385 RV387-RV390 RV579 RV2437-RV2440 RV2739 RV2741 RV2745-RV2748 RV2751-RV2753 RV2758-RV2768 RW3-RW8 RW11 RW12 RWL1 RWL2 = R_0402
CL2 = C_1808
CLRP1-CLRP3 JP6 = SHORTPADS: User Part Number: PART#
CS16 = CK0402101V05_0402-2
D1 DM15 = YSLC05CH_SOT23-3
D6 D7 = PESD5V0U2BT_SOT23-3
D21 D22 DG1 DM16 = AZ1045-04F_DFN2510P10E-10-9
D31-D33 = L05ESDL5V0NA-4_SLP2510P8-10-9
DA6 DA7 = L03ESDL5V0CC3-2_SOT23-3
DC1 = DAN202U_SC70-3
DC3 DC4 DH2 DH4 DH5 DK2 = CH751H-40PT_SOD323-2
DC6 PD1 PD2 = L30ESD24VC3-2_SOT23-3
DL1 DM1 DM5 = AZC199-02SPR7G_SOT23-3
DM12 DM13 = YSUSB2P0-5_SOT-23-6-6
DT2 = AZC099-04SPR7G_SOT23-6
DV1 DV3 DV4 = RB751S40T1G_SOD523-2
FD1-FD4 = FIDUCIAL_C40M80
FG1 FG2 FG4 = AP2330W-7_SC59-3
FU1 = F_MF-MSMF050-2
H1 = H_2P5N
H2 = H_2P5X2P8N
H4 H5 = H_3P2
H6-H11 = H_5P0-G
H13-H15 = H_2P3-G
H17 = H_2P5-G
JCMOS1 PR1802 PRA2 PRA6 PRA9 PRB5 PRB7 PRB9 PRB10 PRB13 PRB14 PRG2 PRG3 PRG6 PRG9 PRM1 PRM4 PRM5 PRV12 PRV20 PRZ76 PRZ77 PRZ79 PRZ85 PRZ87 PRZ102 PRZ103 R24 = R_0603
JCR JHP = ACES_51524-0060N-001_6P
JDIMM1 = FOX_AS0A827-H2RB-7H_260P-T
JDIMM2 = FOX_AS0A827-H2SB-7H_260P-T
JEDP = ACES_51540-03001-001_30P
JFAN = ACES_50271-0040N-001_4P
JFPR JHDD = ACES_51522-00801-001_8P
JHDMI = LOTES_AHDM0064-P001A_19P
JIO = ACES_51522-02601-001_26P
JKB = ACES_50690-0320N-P01_32P
JKBL = ACES_51575-00401-001_4P
JL33 JPHW9 PJ1802 PJV1 PJW1 = JUMP_43X79
JLAN = SINGA_2RJ3081-1A8211F_12P-T
JPHW1 PJ302 PJ305 PJ1002 PJM2 PJW2 = JUMP_43X118
JSPK = ACES_50278-00401-001_4P
JSSD = ARGOS_NFSM0-S6715-TPH4_67P
JTC1 = SINGA_2UB3C02-002111F_24P-T
JTP1 = ACES_51522-01001-001_10P
JTP2 = JXT_FP202DH-004M10M_4P
JWLAN = LOTES_APCI0019-P003H_67P
L12-L14 LM3 LM5-LM7 = MURAT_DLM0NSN900HY2D_4P
LA6 = MURAT_BLM15PX471SN1D_2P
LED1 LED2 = LED_LTW-110DC5-C_3P
LK1 LK2 = MURAT_BLM15BD601SN1D_2P
LL2 = TAI-T_HPC252012F-1R0Y_2P
LV5 LV7 = MURAT_BLM18PG300SN1D_2P
LV6 = KC_FBMA-L11160808601LMA10T_2P
PCB6 PCB7 PCB15 PCB16 PCV5 PCV6 PCV15 PCV16 = C_0603-S3
PCV2 PCV3 PCZ26 PCZ229 = C_6P3X4P5
PCV34 PCV35 = C_X
PCZ68 PCZ69 PCZ215 = C_D1
PCZ248 = C_D7
PD3 = LUDZS3P6BT1G_SOD323-2
PDB1 = BAS40CW_SOT323-3
PDB2 = RB751V-40_SOD323-2
PJ303 = JUMP_43X39
PJ1801 PJ2501 PJ2502 PJM3 = JUMP_43X39_0805
PJP1 = ACES_51483-00801-001_8P-T
PJPB1 = OCTEK_BTJ-08TFBRZB_8P
PL11-PL14 PL305 PL306 PLM2 PLZ3 = 5A_Z80_0805_2P
PL301 PLG1 PLZ1 PLZ2 = L_7X7X3_M
PL302 = L_5X5X3_M_2P
PL303 PL304 PL1002 PL1003 = 3A_Z120_0603_2P
PL1001 PLM1 PLW1 = L_7X7X3_M_2P
PL1801 PL2501 = CHILI_MHCD252012A-1R0M-A8S_2P
PLA1 = L_5X5X3_M
PLB1 = VISHAY_IHLP-2525CZ-01_2P
PLB11 = L_4X4X2_F_2P
PLV3 PLV4 = L_7X7X4_M
PQ2 = L2N7002DW1T1G_SC88-6
PQA1 PQB1 PQM1 = AONH36334_DFN3X3A8-10
PQB2 = 2N7002KW_SOT323-3
PQB11 PQG2 PQZ2 PQZ4 = Q_N_DFN56-8-5
PQB12 PQB13 = AON7506_DFN33-8-5
PQG1 PQZ1 PQZ3 = AON6380_DFN5X6-8-5
PQV1 PQV2 = FDPC5030SG_POWERCLIP56-8-10
PR18 PR302 PR306 PR311 PR1001 PR1003 PR1006 PR1804 PR2501 PRB18 PRB19 PRB22 PRM8 PRM12 PRV1 PRW7 PRZ15 PRZ25 PRZ47 PRZ50 PRZ93-PRZ95 R5261 R5262 RD3 RD5 RD6 RD20 RD22 RD24 RD32 RD33 RF1 RK3 RLED3 RV31 RV202 RV377 = R0402_0OHM
PR19 PRZ53 RC427 = R_0805
PR303 PR308 PR1007 PRA4 PRB6 PRB12 PRG4 PRM3 PRV7 PRV17 PRW6 PRZ82 PRZ84 = R_1206
PRB1 PRB11 = R_1206_4P-D
PTPM1 T62 T63 T78 T79 T81 T90 T96 T103 T140 T178 T231 T232 T242 T243 T254 T257 T258 T276 T305-T307 T323-T329 T354 T365-T372 T377 T402-T406 T408 T2401 T2404-T2406 TS123 = TPC12
PU301 = SY8284BRAC_QFN20_3X3
PU302 = SY8270CTMC_QFN13_4X3
PU1001 PUW1 = SY8286RAC_QFN20_3X3
PU1801 PU2501 = SY8032ABC_SOT23-6
PUA1 PUG1 PUZ2 PUZ3 = RT9610CGQW_WDFN8_2X2
PUB1 = BQ24725ARGRR_QFN20_3P5X3P5
PUM1 = G5616BRZ1U_TQFN20_3X3
PUV1 = RT8812AGQW_WQFN20_3X3
PUZ1 = RT3602AJGQW_WQFN48_6X6
Q9 = MMBF170-7-F_SOT23-3
Q21 = EM5209VF_DFN14_3X2
Q4108 QV3 = 2N7002K_SOT23-3
Q5001 = DMN65D8LDW-7_SOT363-6
QA2 = MMBT3904WH_SOT323-3
QC1 QC7 QG2 = 2N7002DWH_SOT363-6
QG1 = 2N7002KDW_SOT363-6
QG4 QU3 QV146 = 2N7002_SOT23-3
QS1 QWL2 = SSM3K7002FU_SC70-3
QV2 = 2N7002KDWH_SOT363-6
QV5 = LBSS138LT1G_SOT23-3
QV20 QV26 QWL1 = PJ2301_SOT23-3
QV30 = 2N7002DW-7-F_SOT363-6
QV50 = 2N7002W-T-R7_SOT323-3
R163 R170 R171 R173 R5175 R5260 R5263-R5272 RC4 RC49-RC51 RC77 RC91 RC93 RC94 RC100 RC101 RC103-RC107 RC115 RC117 RC118 RC122-RC124 RC127 RC128 RC132 RC165 RC183 RC187 RC201 RC218 RC226 RC227 RC357 RC360 RC374 RC379-RC384 RC401 RC403 RC404 RC409 RC410 RC434 RC459 RC467-RC470 RC472-RC475 RC483 RC491 RC492 RC916 RC926 RC935 RC936 RC940 RC941 RC952-RC959 RC961-RC966 RC978 RC979 RC983-RC987 RC1155 RC1158 RC1159 RG112-RG119 RS47-RS50 RS53 RS54 = R_0201
R201 R202 RA33-RA36 RK1 = R0603_0OHM
R259 R5094 R5178 RC108-RC110 RC230 RK8 RK9 RT3 RT34 = R0201_0OHM
RA51 RA52 RA54 = R0603_0OHM-NPM
RC189-RC191 RL55 = R0805_0OHM
RC471 = MURAT_BLM15EG221SN1D_2P
SW1 = SW_TJG-533-V-T-R_6P
TSL1 = TAI-T_LAN-8700GS_25P
U4018 = YB8251ST23_TSOT-23-3
UA1 = ALC3247-CG_MQFN40_5X5
UC1 = WHL-U42_BGA_1528P-T
UC2 = ACES_91960-0084L_8P-T
UC3 = 74AUP1G07GW_TSSOP5
UC4 = SN74AHC1G08DCKR_SC70-5
UC6 = TPS22966DPUR_SON14_2X3
UC7 = TPS22961DNYR_WSON8
UC11 = G753T11U_SOT23-5
UG1 = G2895TP1U_TSOT23-6
UK1 = KB9022QC_LQFP128_14X14
UL1 = RTL8166EH-CG_QFN32_4X4
UL2 = G524B1T11U_SOT23-5
UT1 = SLB9670VQ1P2-FW4P4X_VQFN32_5X5
UU1 = TPS25810RVCR_QFN20_4X3
UU2 = G524B2T11U_SOT23-5
UV1 = N16S-GT-S-A2_BGA_595P
UV6 UV7 = H5GQ1H24AFR-T2L_BGA_170P
UV12 UV15 = TC7SH08FUF_SSOP5
UV23 = NC7ST32P5X_SC70-5
YC1 = Y_1TJF125BJ1A000A_2P
YC2 = Y_XRCGB24M000F2P51R0_4P
YL1 = Y_XRCGB25M000F2P34R0_4P
YV1 = Y_XRCGB27M000F2P18R0_4P

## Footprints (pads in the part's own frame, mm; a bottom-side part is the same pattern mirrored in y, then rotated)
2N7002_SOT23-3
  oval 1.016x1.524 smd: 1(0,0) 2(0.965,2.083) 3(-0.965,2.083)
2N7002DW-7-F_SOT363-6
  oval 0.432x0.61 smd: 1(0,0) 2(0.65,0) 3(1.3,0) 4(1.3,1.9) 5(0.65,1.9) 6(0,1.9)
2N7002DWH_SOT363-6
  oval 0.356x0.889 smd: 1(0,0) 2(0.65,0) 3(1.3,0) 4(1.3,1.6) 5(0.65,1.6) 6(0,1.6)
2N7002K_SOT23-3
  oval 1.016x1.524 smd: 1(0,0) 2(0.965,2.083) 3(-0.965,2.083)
2N7002KDW_SOT363-6
  oval 0.356x0.889 smd: 1(0,0) 2(0.65,0) 3(1.3,0) 4(1.3,1.6) 5(0.65,1.6) 6(0,1.6)
2N7002KDWH_SOT363-6
  oval 0.356x0.889 smd: 1(0,0) 2(0.65,0) 3(1.3,0) 4(1.3,1.6) 5(0.65,1.6) 6(0,1.6)
2N7002KW_SOT323-3
  oval 0.66x0.864 smd: 1(0,0) 2(0.65,1.85) 3(-0.65,1.85)
2N7002W-T-R7_SOT323-3
  oval 0.813x0.914 smd: 1(0,0) 2(0.65,1.6) 3(-0.65,1.6)
3A_Z120_0603_2P
  rect 0.559x1.041 smd: 1(0,0) 2(1.3,0)
5A_Z80_0805_2P
  rect 0.813x1.397 smd: 1(0,0) 2(1.702,0)
74AUP1G07GW_TSSOP5
  oval 0.381x1.346 smd: 1(0,0) 2(0.65,0) 3(1.3,0) 4(1.3,1.79) 5(0,1.79)
ACES_50271-0040N-001_4P
  oval 0.787x1.6 smd: 1(0,0) 2(-1.25,0) 3(-2.5,0) 4(-3.75,0)
  rect 2.108x2.997 smd: 5(2.55,-2.9) 6(-6.3,-2.9)
ACES_50278-00401-001_4P
  oval 0.787x1.905 smd: 1(0,0) 2(1.25,0) 3(2.5,0) 4(3.75,0)
  rect 1.295x3.353 smd: 5(-2.85,-4.925) 6(6.6,-4.925)
ACES_50690-0320N-P01_32P
  oval 0.305x1.295 smd: 1(0,0) 2(1,0) 3(2,0) 4(3,0) 5(4,0) 6(5,0) 7(6,0) 8(7,0) 9(8,0) 10(9,0) 11(10,0) 12(11,0) 13(12,0) 14(13,0) 15(14,0) 16(15,0) 17(16,0) 18(17,0) 19(18,0) 20(19,0) 21(20,0) 22(21,0) 23(22,0) 24(23,0) 25(24,0) 26(25,0) 27(26,0) 28(27,0) 29(28,0) 30(29,0) 31(30,0) 32(31,0)
  rect 1.803x2.21 smd: 33(-2.4,-3.25) 34(33.4,-3.25)
ACES_51483-00801-001_8P-T
  oval 0.787x1.905 smd: 1(0,0) 2(1.25,0) 3(2.5,0) 4(3.75,0) 5(5,0) 6(6.25,0) 7(7.5,0) 8(8.75,0)
  rect 1.295x3.353 smd: 9(-2.85,-4.925) 10(11.6,-4.925)
ACES_51522-00801-001_8P
  oval 0.305x1.295 smd: 1(0,0) 2(0.5,0) 3(1,0) 4(1.5,0) 5(2,0) 6(2.5,0) 7(3,0) 8(3.5,0)
  rect 2.489x1.905 smd: 9(5.65,-3.3) 10(-2.15,-3.3)
ACES_51522-01001-001_10P
  oval 0.305x1.295 smd: 1(0,0) 2(0.5,0) 3(1,0) 4(1.5,0) 5(2,0) 6(2.5,0) 7(3,0) 8(3.5,0) 9(4,0) 10(4.5,0)
  rect 2.489x1.905 smd: 11(-2.15,-3.3) 12(6.65,-3.3)
ACES_51522-02601-001_26P
  oval 0.305x1.295 smd: 1(0,0) 2(0.5,0) 3(1,0) 4(1.5,0) 5(2,0) 6(2.5,0) 7(3,0) 8(3.5,0) 9(4,0) 10(4.5,0) 11(5,0) 12(5.5,0) 13(6,0) 14(6.5,0) 15(7,0) 16(7.5,0) 17(8,0) 18(8.5,0) 19(9,0) 20(9.5,0) 21(10,0) 22(10.5,0) 23(11,0) 24(11.5,0) 25(12,0) 26(12.5,0)
  rect 2.489x1.905 smd: 27(-2.15,-3.3) 28(14.65,-3.3)
ACES_51524-0060N-001_6P
  oval 0.61x1.295 smd: 1(0,0) 2(1,0) 3(2,0) 4(3,0) 5(4,0) 6(5,0)
  rect 2.159x2.21 smd: 7(-2.825,-3.05) 8(7.825,-3.05)
ACES_51540-03001-001_30P
  oval 0.305x1.092 smd: 1(0,0) 2(-0.5,0) 3(-1,0) 4(-1.5,0) 5(-2,0) 6(-2.5,0) 7(-3,0) 8(-3.5,0) 9(-4,0) 10(-4.5,0) 11(-5,0) 12(-5.5,0) 13(-6,0) 14(-6.5,0) 15(-7,0) 16(-7.5,0) 17(-8,0) 18(-8.5,0) 19(-9,0) 20(-9.5,0) 21(-10,0) 22(-10.5,0) 23(-11,0) 24(-11.5,0) 25(-12,0) 26(-12.5,0) 27(-13,0) 28(-13.5,0) 29(-14,0) 30(-14.5,0)
  rect 0.787x2.489 smd: 31(1.7,-3.6) 32(-16.2,-3.6)
ACES_51575-00401-001_4P
  oval 0.406x0.838 smd: 1(0,0) 2(1,0) 3(2,0) 4(3,0)
  rect 0.787x2.007 smd: 5(-2.2,-3.175) 6(5.2,-3.175)
ACES_91960-0084L_8P-T
  oval 0.889x1.346 smd: 1(0,0) 2(-1.27,0) 3(-2.54,0) 4(-3.81,0) 5(-3.81,-7.35) 6(-2.54,-7.35) 7(-1.27,-7.35) 8(0,-7.35)
ALC3247-CG_MQFN40_5X5
  oval 0.889x0.203 smd: 1(0,0) 2(0,-0.4) 3(0,-0.8) 4(0,-1.2) 5(0,-1.6) 6(0,-2) 7(0,-2.4) 8(0,-2.8) 9(0,-3.2) 10(0,-3.6) 21(5.1,-3.6) 22(5.1,-3.2) 23(5.1,-2.8) 24(5.1,-2.4) 25(5.1,-2) 26(5.1,-1.6) 27(5.1,-1.2) 28(5.1,-0.8) 29(5.1,-0.4) 30(5.1,0)
  oval 0.203x0.889 smd: 11(0.75,-4.35) 12(1.15,-4.35) 13(1.55,-4.35) 14(1.95,-4.35) 15(2.35,-4.35) 16(2.75,-4.35) 17(3.15,-4.35) 18(3.55,-4.35) 19(3.95,-4.35) 20(4.35,-4.35) 31(4.35,0.75) 32(3.95,0.75) 33(3.55,0.75) 34(3.15,0.75) 35(2.75,0.75) 36(2.35,0.75) 37(1.95,0.75) 38(1.55,0.75) 39(1.15,0.75) 40(0.75,0.75)
  rect 3.607x3.607 smd: 41(2.55,-1.8)
AON6380_DFN5X6-8-5
  oval 0.508x0.838 smd: 1(0,0) 2(1.27,0) 3(2.54,0) 4(3.81,0)
  custom 1.15x1.15 smd: 5(1.905,3.69)
AON7506_DFN33-8-5
  oval 0.406x0.991 smd: 1(0,0) 2(0.66,0) 3(1.32,0) 4(1.98,0)
  custom 0.559x0.559 smd: 5(0.99,2.247)
AONH36334_DFN3X3A8-10
  oval 0.457x0.813 smd: 1(0,0) 2(0.65,0) 3(1.3,0) 4(1.95,0) 5(1.95,3.18) 6(1.3,3.18) 7(0.65,3.18) 8(0,3.18)
  rect 2.388x0.991 smd: 9(0.975,2.025)
  rect 2.388x0.508 smd: 10(0.975,0.92)
AP2330W-7_SC59-3
  oval 0.787x0.991 smd: 1(0,0) 2(-0.95,-2.4) 3(0.95,-2.4)
ARGOS_NFSM0-S6715-TPH4_67P
  round 1.092 hole 1.092 unplated: (-0.75,-5.275)
  round 1.6 hole 1.6 unplated: (19.25,-5.275)
  oval 0.305x1.549 smd: 1(0,0) 2(0.25,-7.55) 3(0.5,0) 4(0.75,-7.55) 5(1,0) 6(1.25,-7.55) 7(1.5,0) 8(1.75,-7.55) 9(2,0) 10(2.25,-7.55) 11(2.5,0) 12(2.75,-7.55) 13(3,0) 14(3.25,-7.55) 15(3.5,0) 16(3.75,-7.55) 17(4,0) 18(4.25,-7.55) 19(4.5,0) 20(4.75,-7.55) 21(5,0) 22(5.25,-7.55) 23(5.5,0) 24(5.75,-7.55) 25(6,0) 26(6.25,-7.55) 27(6.5,0) 28(6.75,-7.55) 29(7,0) 30(7.25,-7.55) 31(7.5,0) 32(7.75,-7.55) 33(8,0) 34(8.25,-7.55) 35(8.5,0) 36(8.75,-7.55) 37(9,0) 38(9.25,-7.55) 39(9.5,0) 40(9.75,-7.55) 41(10,0) 42(10.25,-7.55) 43(10.5,0) 44(10.75,-7.55) 45(11,0) 46(11.25,-7.55) 47(11.5,0) 48(11.75,-7.55) 49(12,0) 50(12.25,-7.55) 51(12.5,0) 52(12.75,-7.55) 53(13,0) 54(13.25,-7.55) 55(13.5,0) 56(13.75,-7.55) 57(14,0) 58(14.25,-7.55) 59(16.5,0) 60(16.75,-7.55) 61(17,0) 62(17.25,-7.55) 63(17.5,0) 64(17.75,-7.55) 65(18,0) 66(18.25,-7.55) 67(18.5,0)
  rect 1.194x2.743 smd: 68(-1.1,-0.775) 69(19.6,-0.775)
AZ1045-04F_DFN2510P10E-10-9
  oval 0.254x0.686 smd: 1(0,0) 2(0.5,0) 4(1.5,0) 5(2,0) 6(2,0.875) 7(1.5,0.875) 8(0.5,0.875) 9(0,0.875)
  oval 0.381x1.549 smd: 3(1,0.437)
AZC099-04SPR7G_SOT23-6
  oval 0.559x1.092 smd: 1(0,0) 2(0.95,0) 3(1.9,0) 4(1.9,2.5) 5(0.95,2.5) 6(0,2.5)
AZC199-02SPR7G_SOT23-3
  oval 1.016x1.524 smd: 1(0,0) 2(0.965,2.083) 3(-0.965,2.083)
BAS40CW_SOT323-3
  oval 0.61x0.787 smd: 1(0,0) 2(0.65,1.6) 3(-0.65,1.6)
BQ24725ARGRR_QFN20_3P5X3P5
  oval 0.889x0.254 smd: 1(0,0) 2(0,-0.5) 3(0,-1) 4(0,-1.5) 5(0,-2) 11(3.6,-2) 12(3.6,-1.5) 13(3.6,-1) 14(3.6,-0.5) 15(3.6,0)
  oval 0.254x0.889 smd: 6(0.8,-2.8) 7(1.3,-2.8) 8(1.8,-2.8) 9(2.3,-2.8) 10(2.8,-2.8) 16(2.8,0.8) 17(2.3,0.8) 18(1.8,0.8) 19(1.3,0.8) 20(0.8,0.8)
  rect 2.057x2.057 smd: 21(1.8,-1)
C_6P3X4P5
  oval 3.505x1.6 smd: 1(0,0) 2(5.6,0)
C_0201
  rect 0.381x0.356 smd: 1(0,0) 2(0.584,0)
C_0402
  rect 0.508x0.584 smd: 1(0,0) 2(0.914,0)
C_0603
  rect 0.635x0.889 smd: 1(0,0) 2(1.397,0)
C_0603-S3
  rect 0.635x0.889 smd: 1(0,0) 2(1.397,0)
C_0805
  rect 0.813x1.397 smd: 1(0,0) 2(1.702,0)
C_1808
  rect 1.041x2.311 smd: 1(0,0) 2(4.35,0)
C_D1
  rect 1.803x2.794 smd: 1(0,0) 2(6.5,0)
C_D7
  rect 1.803x2.794 smd: 1(0,0) 2(6.5,0)
C_MP2VLPS330MC4R2
  oval 3.505x1.6 smd: 1(0,0) 2(-5.6,0)
C_X
  rect 1.803x2.896 smd: 1(0,0) 2(6,0)
CH751H-40PT_SOD323-2
  rect 0.711x0.711 smd: 1(0,0) 2(2.33,0)
CHILI_MHCD252012A-1R0M-A8S_2P
  rect 0.787x2.311 smd: 1(0,0) 2(2,0)
CK0402101V05_0402-2
  rect 0.508x0.559 smd: 1(0,0) 2(0.92,0)
DAN202U_SC70-3
  rect 0.787x0.889 smd: 1(0,0) 2(0.65,1.6) 3(-0.65,1.6)
DMN65D8LDW-7_SOT363-6
  oval 0.432x0.61 smd: 1(0,0) 2(0.65,0) 3(1.3,0) 4(1.3,1.9) 5(0.65,1.9) 6(0,1.9)
EM5209VF_DFN14_3X2
  oval 0.203x0.711 smd: 1(0,0) 2(0.4,0) 3(0.8,0) 4(1.2,0) 5(1.6,0) 6(2,0) 7(2.4,0) 8(2.4,2) 9(2,2) 10(1.6,2) 11(1.2,2) 12(0.8,2) 13(0.4,2) 14(0,2)
  rect 2.591x0.991 smd: 15(1.2,1)
F_MF-MSMF050-2
  rect 1.499x3.2 smd: 1(0,0) 2(4.2,0)
FDPC5030SG_POWERCLIP56-8-10
  oval 0.762x0.813 smd: 1(0,0) 2(1.27,0) 3(2.54,0) 4(3.81,0) 5(3.81,5.78) 6(2.54,5.78) 7(1.27,5.78)
  custom 0.202x0.202 smd: 8(0,5.255)
  custom 0.663x0.663 smd: 9(1.905,3.545)
  rect 4.191x1.016 smd: 10(1.905,1.315)
FIDUCIAL_C40M80
  round 1.016 smd: 1(0,0)
FOX_AS0A827-H2RB-7H_260P-T
  round 1.092 hole 1.092 unplated: (-67.775,-4.1)
  round 1.6 hole 1.6 unplated: (1.025,-4.1)
  oval 0.305x1.753 smd: 1(0,0) 2(-0.25,-8.2) 3(-0.5,0) 4(-0.75,-8.2) 5(-1,0) 6(-1.25,-8.2) 7(-1.5,0) 8(-1.75,-8.2) 9(-2,0) 10(-2.25,-8.2) 11(-2.5,0) 12(-2.75,-8.2) 13(-3,0) 14(-3.25,-8.2) 15(-3.5,0) 16(-3.75,-8.2) 17(-4,0) 18(-4.25,-8.2) 19(-4.5,0) 20(-4.75,-8.2) 21(-5,0) 22(-5.25,-8.2) 23(-5.5,0) 24(-5.75,-8.2) 25(-6,0) 26(-6.25,-8.2) 27(-6.5,0) 28(-6.75,-8.2) 29(-7,0) 30(-7.25,-8.2) 31(-7.5,0) 32(-7.75,-8.2) 33(-8,0) 34(-8.25,-8.2) 35(-8.5,0) 36(-8.75,-8.2) 37(-9,0) 38(-9.25,-8.2) 39(-9.5,0) 40(-9.75,-8.2) 41(-10,0) 42(-10.25,-8.2) 43(-10.5,0) 44(-10.75,-8.2) 45(-11,0) 46(-11.25,-8.2) 47(-11.5,0) 48(-11.75,-8.2) 49(-12,0) 50(-12.25,-8.2) 51(-12.5,0) 52(-12.75,-8.2) 53(-13,0) 54(-13.25,-8.2) 55(-13.5,0) 56(-13.75,-8.2) 57(-14,0) 58(-14.25,-8.2) 59(-14.5,0) 60(-14.75,-8.2) 61(-15,0) 62(-15.25,-8.2) 63(-15.5,0) 64(-15.75,-8.2) 65(-16,0) 66(-16.25,-8.2) 67(-16.5,0) 68(-16.75,-8.2) 69(-17,0) 70(-17.25,-8.2) 71(-17.5,0) 72(-17.75,-8.2) 73(-18,0) 74(-18.25,-8.2) 75(-18.5,0) 76(-18.75,-8.2) 77(-19,0) 78(-19.25,-8.2) 79(-19.5,0) 80(-19.75,-8.2) 81(-20,0) 82(-20.25,-8.2) 83(-20.5,0) 84(-20.75,-8.2) 85(-21,0) 86(-21.25,-8.2) 87(-21.5,0) 88(-21.75,-8.2) 89(-22,0) 90(-22.25,-8.2) 91(-22.5,0) 92(-22.75,-8.2) 93(-23,0) 94(-23.25,-8.2) 95(-23.5,0) 96(-23.75,-8.2) 97(-24,0) 98(-24.25,-8.2) 99(-24.5,0) 100(-24.75,-8.2) 101(-25,0) 102(-25.25,-8.2) 103(-25.5,0) 104(-25.75,-8.2) 105(-26,0) 106(-26.25,-8.2) 107(-26.5,0) 108(-26.75,-8.2) 109(-27,0) 110(-27.25,-8.2) 111(-27.5,0) 112(-27.75,-8.2) 113(-28,0) 114(-28.25,-8.2) 115(-28.5,0) 116(-28.75,-8.2) 117(-29,0) 118(-29.25,-8.2) 119(-29.5,0) 120(-29.75,-8.2) 121(-30,0) 122(-30.25,-8.2) 123(-30.5,0) 124(-30.75,-8.2) 125(-31,0) 126(-31.25,-8.2) 127(-31.5,0) 128(-31.75,-8.2) 129(-32,0) 130(-32.25,-8.2) 131(-32.5,0) 132(-32.75,-8.2) 133(-33,0) 134(-33.25,-8.2) 135(-33.5,0) 136(-33.75,-8.2) 137(-34,0) 138(-34.25,-8.2) 139(-34.5,0) 140(-34.75,-8.2) 141(-35,0) 142(-35.25,-8.2) 143(-35.5,0) 144(-35.75,-8.2) 145(-38,0) 146(-38.25,-8.2) 147(-38.5,0) 148(-38.75,-8.2) 149(-39,0) 150(-39.25,-8.2) 151(-39.5,0) 152(-39.75,-8.2) 153(-40,0) 154(-40.25,-8.2) 155(-40.5,0) 156(-40.75,-8.2) 157(-41,0) 158(-41.25,-8.2) 159(-41.5,0) 160(-41.75,-8.2) 161(-42,0) 162(-42.25,-8.2) 163(-42.5,0) 164(-42.75,-8.2) 165(-43,0) 166(-43.25,-8.2) 167(-43.5,0) 168(-43.75,-8.2) 169(-44,0) 170(-44.25,-8.2) 171(-44.5,0) 172(-44.75,-8.2) 173(-45,0) 174(-45.25,-8.2) 175(-45.5,0) 176(-45.75,-8.2) 177(-46,0) 178(-46.25,-8.2) 179(-46.5,0) 180(-46.75,-8.2) 181(-47,0) 182(-47.25,-8.2) 183(-47.5,0) 184(-47.75,-8.2) 185(-48,0) 186(-48.25,-8.2) 187(-48.5,0) 188(-48.75,-8.2) 189(-49,0) 190(-49.25,-8.2) 191(-49.5,0) 192(-49.75,-8.2) 193(-50,0) 194(-50.25,-8.2) 195(-50.5,0) 196(-50.75,-8.2) 197(-51,0) 198(-51.25,-8.2) 199(-51.5,0) 200(-51.75,-8.2) 201(-52,0) 202(-52.25,-8.2) 203(-52.5,0) 204(-52.75,-8.2) 205(-53,0) 206(-53.25,-8.2) 207(-53.5,0) 208(-53.75,-8.2) 209(-54,0) 210(-54.25,-8.2) 211(-54.5,0) 212(-54.75,-8.2) 213(-55,0) 214(-55.25,-8.2) 215(-55.5,0) 216(-55.75,-8.2) 217(-56,0) 218(-56.25,-8.2) 219(-56.5,0) 220(-56.75,-8.2) 221(-57,0) 222(-57.25,-8.2) 223(-57.5,0) 224(-57.75,-8.2) 225(-58,0) 226(-58.25,-8.2) 227(-58.5,0) 228(-58.75,-8.2) 229(-59,0) 230(-59.25,-8.2) 231(-59.5,0) 232(-59.75,-8.2) 233(-60,0) 234(-60.25,-8.2) 235(-60.5,0) 236(-60.75,-8.2) 237(-61,0) 238(-61.25,-8.2) 239(-61.5,0) 240(-61.75,-8.2) 241(-62,0) 242(-62.25,-8.2) 243(-62.5,0) 244(-62.75,-8.2) 245(-63,0) 246(-63.25,-8.2) 247(-63.5,0) 248(-63.75,-8.2) 249(-64,0) 250(-64.25,-8.2) 251(-64.5,0) 252(-64.75,-8.2) 253(-65,0) 254(-65.25,-8.2) 255(-65.5,0) 256(-65.75,-8.2) 257(-66,0) 258(-66.25,-8.2) 259(-66.5,0) 260(-66.75,-8.2)
  rect 3.505x4.597 smd: 261(-67.175,7.9) 262(0.425,7.9)
FOX_AS0A827-H2SB-7H_260P-T
  round 1.6 hole 1.6 unplated: (-1.025,4.1)
  round 1.092 hole 1.092 unplated: (67.775,4.1)
  oval 0.305x1.753 smd: 1(0,0) 2(0.25,8.2) 3(0.5,0) 4(0.75,8.2) 5(1,0) 6(1.25,8.2) 7(1.5,0) 8(1.75,8.2) 9(2,0) 10(2.25,8.2) 11(2.5,0) 12(2.75,8.2) 13(3,0) 14(3.25,8.2) 15(3.5,0) 16(3.75,8.2) 17(4,0) 18(4.25,8.2) 19(4.5,0) 20(4.75,8.2) 21(5,0) 22(5.25,8.2) 23(5.5,0) 24(5.75,8.2) 25(6,0) 26(6.25,8.2) 27(6.5,0) 28(6.75,8.2) 29(7,0) 30(7.25,8.2) 31(7.5,0) 32(7.75,8.2) 33(8,0) 34(8.25,8.2) 35(8.5,0) 36(8.75,8.2) 37(9,0) 38(9.25,8.2) 39(9.5,0) 40(9.75,8.2) 41(10,0) 42(10.25,8.2) 43(10.5,0) 44(10.75,8.2) 45(11,0) 46(11.25,8.2) 47(11.5,0) 48(11.75,8.2) 49(12,0) 50(12.25,8.2) 51(12.5,0) 52(12.75,8.2) 53(13,0) 54(13.25,8.2) 55(13.5,0) 56(13.75,8.2) 57(14,0) 58(14.25,8.2) 59(14.5,0) 60(14.75,8.2) 61(15,0) 62(15.25,8.2) 63(15.5,0) 64(15.75,8.2) 65(16,0) 66(16.25,8.2) 67(16.5,0) 68(16.75,8.2) 69(17,0) 70(17.25,8.2) 71(17.5,0) 72(17.75,8.2) 73(18,0) 74(18.25,8.2) 75(18.5,0) 76(18.75,8.2) 77(19,0) 78(19.25,8.2) 79(19.5,0) 80(19.75,8.2) 81(20,0) 82(20.25,8.2) 83(20.5,0) 84(20.75,8.2) 85(21,0) 86(21.25,8.2) 87(21.5,0) 88(21.75,8.2) 89(22,0) 90(22.25,8.2) 91(22.5,0) 92(22.75,8.2) 93(23,0) 94(23.25,8.2) 95(23.5,0) 96(23.75,8.2) 97(24,0) 98(24.25,8.2) 99(24.5,0) 100(24.75,8.2) 101(25,0) 102(25.25,8.2) 103(25.5,0) 104(25.75,8.2) 105(26,0) 106(26.25,8.2) 107(26.5,0) 108(26.75,8.2) 109(27,0) 110(27.25,8.2) 111(27.5,0) 112(27.75,8.2) 113(28,0) 114(28.25,8.2) 115(28.5,0) 116(28.75,8.2) 117(29,0) 118(29.25,8.2) 119(29.5,0) 120(29.75,8.2) 121(30,0) 122(30.25,8.2) 123(30.5,0) 124(30.75,8.2) 125(31,0) 126(31.25,8.2) 127(31.5,0) 128(31.75,8.2) 129(32,0) 130(32.25,8.2) 131(32.5,0) 132(32.75,8.2) 133(33,0) 134(33.25,8.2) 135(33.5,0) 136(33.75,8.2) 137(34,0) 138(34.25,8.2) 139(34.5,0) 140(34.75,8.2) 141(35,0) 142(35.25,8.2) 143(35.5,0) 144(35.75,8.2) 145(38,0) 146(38.25,8.2) 147(38.5,0) 148(38.75,8.2) 149(39,0) 150(39.25,8.2) 151(39.5,0) 152(39.75,8.2) 153(40,0) 154(40.25,8.2) 155(40.5,0) 156(40.75,8.2) 157(41,0) 158(41.25,8.2) 159(41.5,0) 160(41.75,8.2) 161(42,0) 162(42.25,8.2) 163(42.5,0) 164(42.75,8.2) 165(43,0) 166(43.25,8.2) 167(43.5,0) 168(43.75,8.2) 169(44,0) 170(44.25,8.2) 171(44.5,0) 172(44.75,8.2) 173(45,0) 174(45.25,8.2) 175(45.5,0) 176(45.75,8.2) 177(46,0) 178(46.25,8.2) 179(46.5,0) 180(46.75,8.2) 181(47,0) 182(47.25,8.2) 183(47.5,0) 184(47.75,8.2) 185(48,0) 186(48.25,8.2) 187(48.5,0) 188(48.75,8.2) 189(49,0) 190(49.25,8.2) 191(49.5,0) 192(49.75,8.2) 193(50,0) 194(50.25,8.2) 195(50.5,0) 196(50.75,8.2) 197(51,0) 198(51.25,8.2) 199(51.5,0) 200(51.75,8.2) 201(52,0) 202(52.25,8.2) 203(52.5,0) 204(52.75,8.2) 205(53,0) 206(53.25,8.2) 207(53.5,0) 208(53.75,8.2) 209(54,0) 210(54.25,8.2) 211(54.5,0) 212(54.75,8.2) 213(55,0) 214(55.25,8.2) 215(55.5,0) 216(55.75,8.2) 217(56,0) 218(56.25,8.2) 219(56.5,0) 220(56.75,8.2) 221(57,0) 222(57.25,8.2) 223(57.5,0) 224(57.75,8.2) 225(58,0) 226(58.25,8.2) 227(58.5,0) 228(58.75,8.2) 229(59,0) 230(59.25,8.2) 231(59.5,0) 232(59.75,8.2) 233(60,0) 234(60.25,8.2) 235(60.5,0) 236(60.75,8.2) 237(61,0) 238(61.25,8.2) 239(61.5,0) 240(61.75,8.2) 241(62,0) 242(62.25,8.2) 243(62.5,0) 244(62.75,8.2) 245(63,0) 246(63.25,8.2) 247(63.5,0) 248(63.75,8.2) 249(64,0) 250(64.25,8.2) 251(64.5,0) 252(64.75,8.2) 253(65,0) 254(65.25,8.2) 255(65.5,0) 256(65.75,8.2) 257(66,0) 258(66.25,8.2) 259(66.5,0) 260(66.75,8.2)
  rect 3.505x4.597 smd: 261(-0.425,16.1) 262(67.175,16.1)
G524B1T11U_SOT23-5
  oval 0.533x1.194 smd: 1(0,0) 2(0.95,0) 3(1.9,0) 4(1.9,3) 5(0,3)
G524B2T11U_SOT23-5
  oval 0.533x1.194 smd: 1(0,0) 2(0.95,0) 3(1.9,0) 4(1.9,3) 5(0,3)
G753T11U_SOT23-5
  oval 0.533x1.194 smd: 1(0,0) 2(0.95,0) 3(1.9,0) 4(1.9,3) 5(0,3)
G2895TP1U_TSOT23-6
  oval 0.508x1.194 smd: 1(0,0) 2(0.95,0) 3(1.9,0) 4(1.9,3) 5(0.95,3) 6(0,3)
G5616BRZ1U_TQFN20_3X3
  oval 0.889x0.203 smd: 1(0,0) 2(0,-0.4) 3(0,-0.8) 4(0,-1.2) 5(0,-1.6) 11(3.1,-1.6) 12(3.1,-1.2) 13(3.1,-0.8) 14(3.1,-0.4) 15(3.1,0)
  oval 0.203x0.889 smd: 6(0.75,-2.35) 7(1.15,-2.35) 8(1.55,-2.35) 9(1.95,-2.35) 10(2.35,-2.35) 16(2.35,0.75) 17(1.95,0.75) 18(1.55,0.75) 19(1.15,0.75) 20(0.75,0.75)
  rect 1.6x1.6 smd: 21(1.55,-0.8)
H5GQ1H24AFR-T2L_BGA_170P
  round 0.343 smd: A1(0,0) A2(0.8,0) A3(1.6,0) A4(2.4,0) A5(3.2,0) A10(7.201,0) A11(8.001,0) A12(8.801,0) A13(9.601,0) A14(10.401,0) B1(0,-0.8) B2(0.8,-0.8) B3(1.6,-0.8) B4(2.4,-0.8) B5(3.2,-0.8) B10(7.201,-0.8) B11(8.001,-0.8) B12(8.801,-0.8) B13(9.601,-0.8) B14(10.401,-0.8) C1(0,-1.6) C2(0.8,-1.6) C3(1.6,-1.6) C4(2.4,-1.6) C5(3.2,-1.6) C10(7.201,-1.6) C11(8.001,-1.6) C12(8.801,-1.6) C13(9.601,-1.6) C14(10.401,-1.6) D1(0,-2.4) D2(0.8,-2.4) D3(1.6,-2.4) D4(2.4,-2.4) D5(3.2,-2.4) D10(7.201,-2.4) D11(8.001,-2.4) D12(8.801,-2.4) D13(9.601,-2.4) D14(10.401,-2.4) E1(0,-3.2) E2(0.8,-3.2) E3(1.6,-3.2) E4(2.4,-3.2) E5(3.2,-3.2) E10(7.201,-3.2) E11(8.001,-3.2) E12(8.801,-3.2) E13(9.601,-3.2) E14(10.401,-3.2) F1(0,-4) F2(0.8,-4) F3(1.6,-4) F4(2.4,-4) F5(3.2,-4) F10(7.201,-4) F11(8.001,-4) F12(8.801,-4) F13(9.601,-4) F14(10.401,-4) G1(0,-4.801) G2(0.8,-4.801) G3(1.6,-4.801) G4(2.4,-4.801) G5(3.2,-4.801) G10(7.201,-4.801) G11(8.001,-4.801) G12(8.801,-4.801) G13(9.601,-4.801) G14(10.401,-4.801) H1(0,-5.601) H2(0.8,-5.601) H3(1.6,-5.601) H4(2.4,-5.601) H5(3.2,-5.601) H10(7.201,-5.601) H11(8.001,-5.601) H12(8.801,-5.601) H13(9.601,-5.601) H14(10.401,-5.601) J1(0,-6.401) J2(0.8,-6.401) J3(1.6,-6.401) J4(2.4,-6.401) J5(3.2,-6.401) J10(7.201,-6.401) J11(8.001,-6.401) J12(8.801,-6.401) J13(9.601,-6.401) J14(10.401,-6.401) K1(0,-7.201) K2(0.8,-7.201) K3(1.6,-7.201) K4(2.4,-7.201) K5(3.2,-7.201) K10(7.201,-7.201) K11(8.001,-7.201) K12(8.801,-7.201) K13(9.601,-7.201) K14(10.401,-7.201) L1(0,-8.001) L2(0.8,-8.001) L3(1.6,-8.001) L4(2.4,-8.001) L5(3.2,-8.001) L10(7.201,-8.001) L11(8.001,-8.001) L12(8.801,-8.001) L13(9.601,-8.001) L14(10.401,-8.001) M1(0,-8.801) M2(0.8,-8.801) M3(1.6,-8.801) M4(2.4,-8.801) M5(3.2,-8.801) M10(7.201,-8.801) M11(8.001,-8.801) M12(8.801,-8.801) M13(9.601,-8.801) M14(10.401,-8.801) N1(0,-9.601) N2(0.8,-9.601) N3(1.6,-9.601) N4(2.4,-9.601) N5(3.2,-9.601) N10(7.201,-9.601) N11(8.001,-9.601) N12(8.801,-9.601) N13(9.601,-9.601) N14(10.401,-9.601) P1(0,-10.401) P2(0.8,-10.401) P3(1.6,-10.401) P4(2.4,-10.401) P5(3.2,-10.401) P10(7.201,-10.401) P11(8.001,-10.401) P12(8.801,-10.401) P13(9.601,-10.401) P14(10.401,-10.401) R1(0,-11.201) R2(0.8,-11.201) R3(1.6,-11.201) R4(2.4,-11.201) R5(3.2,-11.201) R10(7.201,-11.201) R11(8.001,-11.201) R12(8.801,-11.201) R13(9.601,-11.201) R14(10.401,-11.201) T1(0,-12.002) T2(0.8,-12.002) T3(1.6,-12.002) T4(2.4,-12.002) T5(3.2,-12.002) T10(7.201,-12.002) T11(8.001,-12.002) T12(8.801,-12.002) T13(9.601,-12.002) T14(10.401,-12.002) U1(0,-12.802) U2(0.8,-12.802) U3(1.6,-12.802) U4(2.4,-12.802) U5(3.2,-12.802) U10(7.201,-12.802) U11(8.001,-12.802) U12(8.801,-12.802) U13(9.601,-12.802) U14(10.401,-12.802)
H_2P3-G
  round 2.819 hole 2.311: 1(0,0)
H_2P5-G
  round 2.997 hole 2.489: 1(0,0)
H_2P5N
  round 2.489 hole 2.489 unplated: (0,0)
H_2P5X2P8N
  oval 2.489x2.794 hole 2.489x2.794 unplated: (0,0)
H_3P2
  round 3.708 hole 3.2: 1(0,0)
H_5P0-G
  round 5.512 hole 5.004: 1(0,0)
JUMP_43X39
  custom 0.191x0.191 smd: 1(0,0) 2(0.914,0)
JUMP_43X39_0805
  custom 0.191x0.191 smd: 1(0,0) 2(0,-0.914)
JUMP_43X79
  custom 0.187x0.187 smd: 1(0,0) 2(1.1,0)
JUMP_43X118
  custom 0.187x0.187 smd: 1(0,0) 2(1.1,0)
JXT_FP202DH-004M10M_4P
  oval 0.61x1.448 smd: 1(0,0) 2(1,0) 3(2,0) 4(3,0)
  rect 2.159x2.21 smd: 5(-2.825,-3.125) 6(5.825,-3.125)
KB9022QC_LQFP128_14X14
  oval 1.753x0.203 smd: 1(0,0) 2(0,-0.4) 3(0,-0.8) 4(0,-1.2) 5(0,-1.6) 6(0,-2) 7(0,-2.4) 8(0,-2.8) 9(0,-3.2) 10(0,-3.6) 11(0,-4) 12(0,-4.4) 13(0,-4.8) 14(0,-5.2) 15(0,-5.6) 16(0,-6) 17(0,-6.4) 18(0,-6.8) 19(0,-7.2) 20(0,-7.6) 21(0,-8) 22(0,-8.4) 23(0,-8.8) 24(0,-9.2) 25(0,-9.6) 26(0,-10) 27(0,-10.4) 28(0,-10.8) 29(0,-11.2) 30(0,-11.6) 31(0,-12) 32(0,-12.4) 65(15.654,-12.4) 66(15.654,-12) 67(15.654,-11.6) 68(15.654,-11.2) 69(15.654,-10.8) 70(15.654,-10.4) 71(15.654,-10) 72(15.654,-9.6) 73(15.654,-9.2) 74(15.654,-8.8) 75(15.654,-8.4) 76(15.654,-8) 77(15.654,-7.6) 78(15.654,-7.2) 79(15.654,-6.8) 80(15.654,-6.4) 81(15.654,-6) 82(15.654,-5.6) 83(15.654,-5.2) 84(15.654,-4.8) 85(15.654,-4.4) 86(15.654,-4) 87(15.654,-3.6) 88(15.654,-3.2) 89(15.654,-2.8) 90(15.654,-2.4) 91(15.654,-2) 92(15.654,-1.6) 93(15.654,-1.2) 94(15.654,-0.8) 95(15.654,-0.4) 96(15.654,0)
  oval 0.203x1.753 smd: 33(1.627,-14.027) 34(2.027,-14.027) 35(2.427,-14.027) 36(2.827,-14.027) 37(3.227,-14.027) 38(3.627,-14.027) 39(4.027,-14.027) 40(4.427,-14.027) 41(4.827,-14.027) 42(5.227,-14.027) 43(5.627,-14.027) 44(6.027,-14.027) 45(6.427,-14.027) 46(6.827,-14.027) 47(7.227,-14.027) 48(7.627,-14.027) 49(8.027,-14.027) 50(8.427,-14.027) 51(8.827,-14.027) 52(9.227,-14.027) 53(9.627,-14.027) 54(10.027,-14.027) 55(10.427,-14.027) 56(10.827,-14.027) 57(11.227,-14.027) 58(11.627,-14.027) 59(12.027,-14.027) 60(12.427,-14.027) 61(12.827,-14.027) 62(13.227,-14.027) 63(13.627,-14.027) 64(14.027,-14.027) 97(14.027,1.627) 98(13.627,1.627) 99(13.227,1.627) 100(12.827,1.627) 101(12.427,1.627) 102(12.027,1.627) 103(11.627,1.627) 104(11.227,1.627) 105(10.827,1.627) 106(10.427,1.627) 107(10.027,1.627) 108(9.627,1.627) 109(9.227,1.627) 110(8.827,1.627) 111(8.427,1.627) 112(8.027,1.627) 113(7.627,1.627) 114(7.227,1.627) 115(6.827,1.627) 116(6.427,1.627) 117(6.027,1.627) 118(5.627,1.627) 119(5.227,1.627) 120(4.827,1.627) 121(4.427,1.627) 122(4.027,1.627) 123(3.627,1.627) 124(3.227,1.627) 125(2.827,1.627) 126(2.427,1.627) 127(2.027,1.627) 128(1.627,1.627)
